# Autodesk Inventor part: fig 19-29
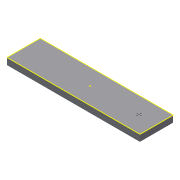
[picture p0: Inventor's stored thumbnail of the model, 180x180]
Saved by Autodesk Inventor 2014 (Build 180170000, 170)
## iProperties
Created: 2013-07
Part Number: fig 19-29
Material: Generic
Document SubType Name: Modeling
Designer: CADCIM
Density: 1 g/cm^3
Appearance: Default
Author: CADCIM
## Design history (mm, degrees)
sketch "Sketch1"
  geometry: L1 (-20, 5)-(20, 5); L2 (20, 5)-(20, -5); L3 (20, -5)-(-20, -5); L4 (-20, -5)-(-20, 5); L5 (-20, 5)-(20, -5); L6 (20, 5)-(-20, -5); 1 further point
  constraints: 12 end point, 2 midpoint, 2 parallel, 1 horizontal, 1 perpendicular
  dimensions: "d0" = 40 distance of L2.end L3.end; "d1" = 10 distance of L1.end L2.end
extrude "Extrusion1" new body sketch "Sketch1" distance "d2" = 2; taper "d3" = 0 deg
sketch "Sketch2"
  geometry: L1 (20, 5)-(-20, 5) reference; L2 (-20, 5)-(-20, -5) reference; L3 (-20, -5)-(20, -5) reference; L4 (20, -5)-(20, 5) reference; 2 further points
body "Solid1"
